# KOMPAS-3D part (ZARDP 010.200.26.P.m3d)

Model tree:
1. Плоскость XY
2. Плоскость ZX
3. Плоскость ZY
4. Ось X
5. Ось Y
6. Ось Z
7. Начало координат
8. Булева операция:1
9. Булева операция:6
10. Булева операция:7
11. Булева операция:8
